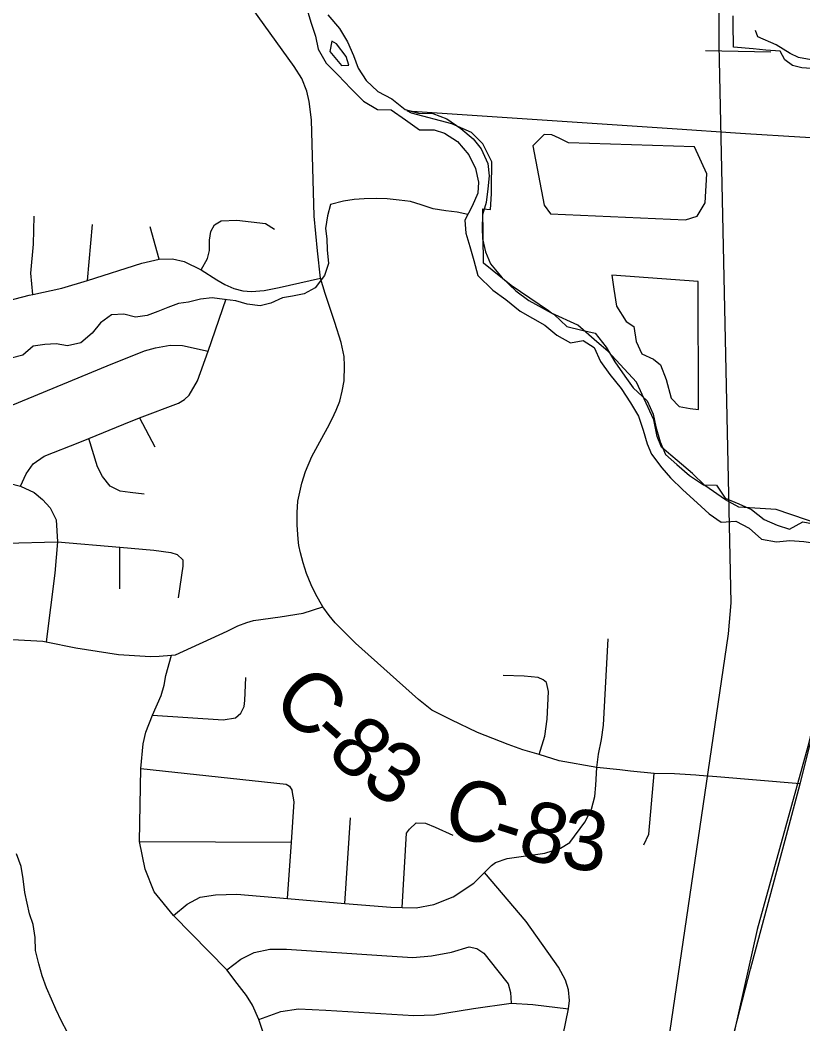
# Model space of a CAD drawing. Extents: x 0 to 34, y 0 to 22.
# Drawn here: x 4.322 to 5.063, y 18.158 to 19.107 of the extents above; entities that cross this region are included whole.
import ezdxf

# ---------------------------------------------------------------- set-up
doc = ezdxf.new("R2010")
doc.units = 0
for name, color, linetype in [('GM_X_City_Street', 7, 'Continuous'), ('GM_X_Corporation', 7, 'Continuous'), ('GM_X_County_Road', 7, 'Continuous'), ('GM_X_County_Road_Text', 7, 'Continuous'), ('GM_X_Major_River', 7, 'Continuous'), ('GM_X_Minor_Lake', 7, 'Continuous'), ('GM_X_Minor_River', 7, 'Continuous'), ('GM_X_Rail_Line', 7, 'Continuous'), ('GM_X_State_Route', 7, 'Continuous'), ('GM_X_Township_Road', 7, 'Continuous')]:
    doc.layers.add(name, color=color, linetype=linetype)

msp = doc.modelspace()

# ---------------------------------------------------------------- linework, layer by layer
at = {"layer": 'GM_X_City_Street'}
for p, q in [((4.38555, 18.86075), (4.39028, 18.91383)), ((4.45361, 18.88093), (4.44496, 18.9117)), ((4.43498, 18.731), (4.44926, 18.7035)), ((4.41612, 18.56929), (4.41612, 18.60863)), ((4.62907, 18.27172), (4.63468, 18.35253)), ((4.43502, 18.33033), (4.57869, 18.32953))]:
    msp.add_line(p, q, dxfattribs=at)
for points in [[(4.33382, 18.84764), (4.3321, 18.8678), (4.33448, 18.8951), (4.33533, 18.92167)], [(4.49327, 18.87101), (4.49915, 18.88166), (4.50099, 18.88937), (4.50099, 18.89892), (4.50246, 18.90737), (4.50576, 18.91362), (4.51201, 18.91729), (4.52707, 18.91802), (4.55425, 18.91472), (4.56269, 18.90958)], [(4.30388, 18.84021), (4.33059, 18.84694), (4.33382, 18.84764), (4.36149, 18.85359), (4.38555, 18.86075), (4.43708, 18.87726), (4.45361, 18.88093), (4.46609, 18.8813), (4.47712, 18.87872), (4.49327, 18.87101), (4.50815, 18.86146), (4.5155, 18.85706), (4.52413, 18.8532), (4.53276, 18.85099), (4.54084, 18.85044), (4.55296, 18.85154), (4.56692, 18.85412), (4.60604, 18.86311)], [(4.32218, 18.66628), (4.32761, 18.678), (4.33423, 18.68737), (4.34463, 18.69477), (4.37829, 18.70783), (4.38687, 18.71135), (4.42001, 18.72493), (4.43498, 18.731), (4.47165, 18.74487), (4.4774, 18.74819), (4.4819, 18.75231), (4.48987, 18.76581), (4.49974, 18.79403), (4.51698, 18.8434)], [(4.26401, 18.6743), (4.26874, 18.70071), (4.27171, 18.71813), (4.27638, 18.7245), (4.28715, 18.7319), (4.40426, 18.78028), (4.43947, 18.79445), (4.45016, 18.79729), (4.46388, 18.7997), (4.47565, 18.79949), (4.49974, 18.79403)], [(3.97531, 18.7522), (3.97875, 18.73865), (3.98594, 18.71497), (3.99255, 18.70194), (3.99813, 18.69576), (4.003, 18.69149), (4.01396, 18.68825), (4.0371, 18.68709), (4.13206, 18.68231), (4.20712, 18.67785), (4.26401, 18.6743), (4.28269, 18.67312), (4.2971, 18.67133), (4.31112, 18.66918), (4.32218, 18.66628), (4.33528, 18.66039), (4.34314, 18.65379), (4.35022, 18.64568), (4.35589, 18.63435), (4.3572, 18.61358), (4.35483, 18.58408), (4.34643, 18.51911)], [(4.43936, 18.65887), (4.42608, 18.66026), (4.41661, 18.66157), (4.4072, 18.6663), (4.39976, 18.67554), (4.39498, 18.68474), (4.38687, 18.71135)], [(4.28979, 18.58032), (4.29277, 18.59811), (4.29555, 18.60528), (4.29982, 18.61052), (4.30822, 18.61227), (4.3572, 18.61358)], [(4.3572, 18.61358), (4.41612, 18.60863), (4.4483, 18.60592), (4.4646, 18.60372), (4.47064, 18.60172), (4.47588, 18.59668), (4.47576, 18.59061), (4.47144, 18.56069)], [(4.31459, 18.52139), (4.34344, 18.51972), (4.34643, 18.51911), (4.37448, 18.51346), (4.41502, 18.50703), (4.44539, 18.50533), (4.45337, 18.50557), (4.46531, 18.50652), (4.46897, 18.5068), (4.51793, 18.52927), (4.5279, 18.53409), (4.53637, 18.53742), (4.54291, 18.53942), (4.56798, 18.54277), (4.58986, 18.54616), (4.60838, 18.55211)], [(4.86769, 18.40011), (4.86926, 18.41287), (4.87223, 18.42667), (4.87412, 18.4402), (4.87845, 18.5219)], [(4.55144, 18.15043), (4.54768, 18.16195), (4.54191, 18.17541), (4.53604, 18.18461), (4.52729, 18.1958), (4.51743, 18.20887), (4.4671, 18.26014), (4.44865, 18.28256), (4.44016, 18.30416), (4.43502, 18.33033), (4.43609, 18.39922), (4.43838, 18.4226), (4.44099, 18.43362), (4.44724, 18.44964), (4.45526, 18.46824), (4.45825, 18.47812), (4.45972, 18.48724), (4.46531, 18.50652)], [(4.44724, 18.44964), (4.51397, 18.44535), (4.52575, 18.44731), (4.53067, 18.45151), (4.53407, 18.45797), (4.53441, 18.46367), (4.53544, 18.48532)], [(4.81309, 18.41247), (4.81839, 18.42991), (4.82083, 18.44588), (4.82191, 18.47212), (4.82001, 18.48051), (4.81677, 18.48321), (4.81217, 18.48538), (4.79891, 18.48673), (4.77917, 18.48727)], [(4.43609, 18.39922), (4.57364, 18.38452), (4.5767, 18.38263), (4.57938, 18.37846)], [(4.4671, 18.26014), (4.47991, 18.27094), (4.49243, 18.27745), (4.50687, 18.2798), (4.52703, 18.28028), (4.57501, 18.27625), (4.62907, 18.27172), (4.67281, 18.26805), (4.68346, 18.26777), (4.69678, 18.26741), (4.7135, 18.27052), (4.73172, 18.27782), (4.75143, 18.29083), (4.76146, 18.30093), (4.76808, 18.3076), (4.77187, 18.31028), (4.78288, 18.31413), (4.81862, 18.31924), (4.83343, 18.32386), (4.84215, 18.32921), (4.85643, 18.34849), (4.86268, 18.36085), (4.86565, 18.37274), (4.8667, 18.38341), (4.86769, 18.40011)], [(4.91208, 18.32718), (4.91681, 18.33727), (4.92185, 18.39465)], [(4.57501, 18.27625), (4.57869, 18.32953), (4.58134, 18.36785), (4.57938, 18.37846)], [(4.68346, 18.26777), (4.68764, 18.33798), (4.69029, 18.34178), (4.69672, 18.34789), (4.70547, 18.34755), (4.71462, 18.3438), (4.73141, 18.33629)], [(4.83137, 18.21148), (4.8007, 18.25461), (4.76146, 18.30093)], [(4.51743, 18.20887), (4.53073, 18.21884), (4.54336, 18.22527), (4.55809, 18.22848), (4.57415, 18.22848), (4.66888, 18.22206), (4.69347, 18.22062), (4.71131, 18.22194), (4.73014, 18.2256), (4.74676, 18.23048), (4.75407, 18.22903), (4.76072, 18.22449), (4.77401, 18.20776), (4.78365, 18.19547), (4.78609, 18.18749), (4.78653, 18.17724)], [(4.55311, 18.11912), (4.6157, 18.11121), (4.70262, 18.10077), (4.74862, 18.10669), (4.80564, 18.11493), (4.81969, 18.12107), (4.83103, 18.13506), (4.83598, 18.14719), (4.84104, 18.17181), (4.84181, 18.17979), (4.84087, 18.18993), (4.8379, 18.19898), (4.83137, 18.21148)], [(4.54768, 18.16195), (4.5685, 18.16927), (4.58534, 18.17192), (4.61127, 18.17082), (4.69458, 18.16572), (4.71408, 18.16639), (4.75108, 18.17237), (4.78653, 18.17724), (4.80714, 18.17613), (4.84104, 18.17181)]]:
    msp.add_lwpolyline(points, dxfattribs=at)
at = {"layer": 'GM_X_Corporation'}
for points in [[(5.09183, 19.05987), (5.06178, 19.06204), (5.05293, 19.06419), (5.0457, 19.06974), (5.04133, 19.07774), (5.02768, 19.07888), (5.01579, 19.07987), (4.99707, 19.08143), (4.99701, 19.08595), (4.99685, 19.0995), (4.9968, 19.10372), (4.99665, 19.11137)], [(5.08109, 18.62959), (5.03738, 18.64436), (5.00204, 18.6466), (4.98957, 18.65331), (4.96997, 18.66686), (4.9582, 18.67838), (4.94366, 18.69069), (4.93777, 18.69567), (4.92878, 18.70328), (4.92467, 18.71345), (4.92169, 18.7292), (4.90529, 18.76469), (4.87812, 18.79405), (4.8678, 18.80297), (4.84977, 18.81855), (4.82493, 18.82998), (4.82191, 18.83204), (4.78662, 18.85616), (4.76058, 18.87714), (4.75996, 18.92857), (4.76702, 18.92817), (4.7681, 18.94298), (4.76814, 18.94819), (4.7683, 18.97308), (4.7598, 18.98999), (4.74916, 19.00098), (4.73043, 19.00896), (4.69231, 19.01911), (4.68815, 19.02126), (4.94366, 19.00433), (4.99883, 19.00063), (5.00831, 19.00003), (5.05997, 18.99684), (5.11381, 18.99352)]]:
    msp.add_lwpolyline(points, dxfattribs=at)
at = {"layer": 'GM_X_County_Road'}
msp.add_line((5.06027, 18.38488), (4.98121, 18.39138), dxfattribs=at)
for points in [[(4.61448, 18.54413), (4.60838, 18.55211), (4.60163, 18.56378), (4.59746, 18.57311), (4.5951, 18.57836), (4.59295, 18.58383), (4.58974, 18.5939), (4.58738, 18.60322), (4.58575, 18.61023), (4.58501, 18.6162), (4.58409, 18.62988), (4.584, 18.64145), (4.58483, 18.6522), (4.5885, 18.66909), (4.59199, 18.6802), (4.598, 18.69449), (4.60732, 18.71188), (4.61274, 18.72143), (4.61724, 18.73015), (4.6211, 18.73823), (4.62449, 18.74686), (4.62679, 18.75605), (4.62863, 18.76596), (4.62899, 18.78029), (4.62844, 18.7891), (4.62587, 18.80215), (4.61963, 18.82106), (4.61045, 18.84843), (4.60604, 18.86311), (4.60328, 18.88901), (4.60016, 18.9217), (4.59759, 19.01279), (4.59559, 19.03019), (4.59312, 19.03981), (4.58844, 19.05189), (4.5813, 19.06343), (4.51866, 19.15025)], [(4.8896, 18.39787), (4.86769, 18.40011), (4.83218, 18.40653), (4.81309, 18.41247), (4.79776, 18.41685), (4.78384, 18.42186), (4.7549, 18.43344), (4.72972, 18.44532), (4.71157, 18.4544), (4.69905, 18.46441), (4.6393, 18.51791), (4.61996, 18.53695), (4.61448, 18.54413)], [(4.9615, 18.39295), (4.94108, 18.39433), (4.92185, 18.39465), (4.89946, 18.39686), (4.8896, 18.39787)], [(4.98121, 18.39138), (4.96441, 18.39276), (4.9615, 18.39295)]]:
    msp.add_lwpolyline(points, dxfattribs=at)
at = {"layer": 'GM_X_Major_River'}
for points in [[(4.59429, 19.1148), (4.59727, 19.10416), (4.60139, 19.09199), (4.60398, 19.07983), (4.6115, 19.0665), (4.62282, 19.05506), (4.6349, 19.04247), (4.64698, 19.03064), (4.66021, 19.0226), (4.6731, 19.02216), (4.68671, 19.01298), (4.69994, 19.00343), (4.71359, 19.00336), (4.72344, 19.00028), (4.73592, 18.99224), (4.74647, 18.97967), (4.75286, 18.96673), (4.75583, 18.9538), (4.75502, 18.94356), (4.74965, 18.93106), (4.74276, 18.9178), (4.74384, 18.90565), (4.74757, 18.8931), (4.7513, 18.8798), (4.75502, 18.86573), (4.76936, 18.85161), (4.78146, 18.84282), (4.79506, 18.83175), (4.81851, 18.81873), (4.82984, 18.80918), (4.8427, 18.80191), (4.85485, 18.80412), (4.86505, 18.79762), (4.87106, 18.78431), (4.8801, 18.77211), (4.89065, 18.75878), (4.89969, 18.74506), (4.90722, 18.7325), (4.9117, 18.71919), (4.91543, 18.70626), (4.91956, 18.69675), (4.92935, 18.6838), (4.93727, 18.67427), (4.94897, 18.66283), (4.96257, 18.65061), (4.9739, 18.64031), (4.98524, 18.63228), (4.99927, 18.63335), (5.01176, 18.62646), (5.02346, 18.61615), (5.03787, 18.61381)], [(4.61324, 19.11205), (4.62418, 19.09909), (4.6317, 19.08652), (4.63733, 19.07359), (4.64182, 19.0618), (4.64935, 19.04999), (4.6603, 19.03969), (4.67354, 19.03279), (4.68638, 19.02248), (4.69888, 19.019), (4.71253, 19.01893), (4.72578, 19.01393), (4.73901, 19.00476), (4.75072, 18.99483), (4.75826, 18.9853), (4.76464, 18.97161), (4.76572, 18.95983), (4.76452, 18.94769), (4.76294, 18.93479), (4.75947, 18.92304), (4.75903, 18.91051), (4.75936, 18.90026), (4.76234, 18.88809), (4.76721, 18.87668), (4.77814, 18.86334), (4.79098, 18.85113), (4.80345, 18.84196), (4.81593, 18.83506), (4.82728, 18.82855), (4.83936, 18.81749), (4.85338, 18.814), (4.86626, 18.8109), (4.87644, 18.79795), (4.88471, 18.78386), (4.89413, 18.77053), (4.90204, 18.75948), (4.91525, 18.74689), (4.92088, 18.73433), (4.92347, 18.72255), (4.92758, 18.70811)], [(4.61691, 19.08736), (4.61497, 19.07749), (4.6259, 19.06415), (4.63311, 19.0645)], [(4.63311, 19.0645), (4.6305, 19.07286), (4.62145, 19.08468), (4.61691, 19.08736)], [(4.92758, 18.70811), (4.93283, 18.69631), (4.9434, 18.68677), (4.95549, 18.67646), (4.96872, 18.66767), (4.98085, 18.66723), (4.98914, 18.65504), (5.00201, 18.64966), (5.01412, 18.64429), (5.02621, 18.63474), (5.03832, 18.62937), (5.05006, 18.62552), (5.06261, 18.63267), (5.07436, 18.63034)], [(5.03787, 18.61381), (5.05039, 18.61489), (5.06366, 18.61406), (5.07654, 18.61211), (5.09206, 18.60558), (5.10531, 18.6002), (5.11817, 18.59292), (5.13026, 18.58414), (5.14276, 18.58028), (5.15562, 18.57187), (5.16504, 18.56005), (5.17105, 18.54788), (5.17516, 18.53495), (5.17737, 18.52241), (5.17769, 18.51064), (5.17422, 18.49851), (5.1719, 18.48827), (5.16576, 18.47539), (5.14138, 18.45348), (5.13336, 18.44175), (5.13216, 18.42999), (5.13248, 18.41746), (5.13143, 18.40594)]]:
    msp.add_lwpolyline(points, dxfattribs=at)
at = {"layer": 'GM_X_Minor_Lake'}
for points in [[(4.96001, 18.98734), (4.84089, 18.9912), (4.8322, 18.99547), (4.82502, 18.99858), (4.81782, 18.99903), (4.80708, 18.98813)], [(4.80708, 18.98813), (4.81792, 18.93222), (4.82391, 18.92381), (4.95175, 18.91835), (4.96278, 18.92165), (4.97012, 18.93448), (4.9719, 18.96179), (4.96001, 18.98734)], [(4.9637, 18.85977), (4.88179, 18.86591), (4.88394, 18.85261), (4.88644, 18.83664), (4.8954, 18.82213), (4.90257, 18.8175), (4.90508, 18.80305), (4.91029, 18.79161), (4.92124, 18.78657), (4.92802, 18.78118), (4.9332, 18.76709), (4.93796, 18.74958), (4.94547, 18.74153), (4.95608, 18.73991), (4.96404, 18.73869)], [(4.96404, 18.73869), (4.9637, 18.85977)]]:
    msp.add_lwpolyline(points, dxfattribs=at)
at = {"layer": 'GM_X_Minor_River'}
for points in [[(4.74566, 18.92338), (4.73546, 18.92543), (4.72486, 18.92667), (4.71275, 18.92868), (4.70142, 18.93259), (4.69121, 18.93572), (4.68061, 18.93696), (4.66925, 18.93821), (4.65902, 18.93831), (4.64765, 18.93804), (4.63817, 18.93737), (4.62793, 18.93595), (4.61577, 18.93265), (4.61264, 18.92205), (4.61102, 18.90991), (4.61207, 18.90041), (4.61235, 18.88977), (4.61375, 18.87685), (4.60986, 18.86549), (4.60104, 18.85381), (4.59075, 18.84821), (4.57974, 18.84604), (4.57026, 18.84461), (4.55922, 18.8394), (4.54896, 18.83684), (4.53685, 18.83847), (4.52589, 18.84162), (4.51529, 18.84286), (4.50356, 18.84449), (4.49255, 18.84308), (4.48116, 18.84053), (4.47168, 18.8391), (4.46179, 18.8354), (4.45228, 18.83169), (4.44201, 18.82762), (4.43101, 18.8262), (4.42005, 18.82896), (4.40829, 18.82832), (4.39799, 18.82082), (4.38994, 18.81103), (4.37925, 18.80201), (4.36672, 18.7991), (4.35613, 18.8011), (4.34513, 18.80044), (4.33412, 18.79865), (4.32458, 18.79039), (4.31356, 18.78746)], [(4.36653, 18.15011), (4.36094, 18.16042), (4.35573, 18.17148), (4.35165, 18.18101), (4.34682, 18.19169), (4.34276, 18.20312), (4.33945, 18.21455), (4.33653, 18.22711), (4.33626, 18.23926), (4.3341, 18.25182), (4.33078, 18.26172), (4.3286, 18.27199), (4.32642, 18.28189), (4.32464, 18.29482), (4.32285, 18.30661), (4.31841, 18.31842)]]:
    msp.add_lwpolyline(points, dxfattribs=at)
at = {"layer": 'GM_X_Rail_Line'}
for points in [[(4.80228, 17.25055), (4.8213, 17.366), (4.86303, 17.64736), (4.90372, 17.9242), (4.99245, 18.52676), (4.99499, 18.55593), (4.98355, 19.08363), (4.98587, 19.75382), (4.99256, 19.90285), (5.013, 20.2642), (5.02024, 20.38635), (5.05041, 20.9)], [(5.013, 20.2642), (5.1449, 19.80142), (5.15727, 19.72918), (5.15969, 19.50896), (5.13444, 19.0127), (5.12013, 18.63864), (5.06738, 18.42023), (5.01943, 18.24707), (4.96758, 18.0163), (4.96155, 17.92727), (4.95651, 17.64256), (4.86303, 17.64736)]]:
    msp.add_lwpolyline(points, dxfattribs=at)
at = {"layer": 'GM_X_State_Route'}
for points in [[(5.0472, 18.33612), (5.06027, 18.38488), (5.0795, 18.46117), (5.1045, 18.55414), (5.10555, 18.55897)], [(4.95945, 17.87106), (4.96194, 17.92079), (4.96695, 17.99186), (4.97424, 18.03982), (4.98786, 18.11159), (5.01323, 18.20936), (5.0472, 18.33612)]]:
    msp.add_lwpolyline(points, dxfattribs=at)
at = {"layer": 'GM_X_Township_Road'}
msp.add_line((4.97042, 19.07854), (5.03227, 19.07717), dxfattribs=at)
msp.add_lwpolyline([(5.1325, 18.91193), (5.12293, 18.91011), (5.11676, 18.91231), (5.11234, 18.91408), (5.10882, 18.91783), (5.10926, 18.92511), (5.11279, 18.93327), (5.11587, 18.94054), (5.11896, 18.95444), (5.12028, 18.99899), (5.12249, 19.03736), (5.11984, 19.05104), (5.11499, 19.05898), (5.10926, 19.06382), (5.09692, 19.06779), (5.07046, 19.06956), (5.05855, 19.07176), (5.05062, 19.07573), (5.03739, 19.08368), (5.02008, 19.09142), (5.01777, 19.09728)], dxfattribs=at)

# ---------------------------------------------------------------- texts
at = {"layer": 'GM_X_County_Road_Text'}
for s, rotation, p in [('C', 317.07338, (4.55796, 18.46021)), ('-', 318.0911, (4.59269, 18.42792)), ('8', 318.65272, (4.61036, 18.41207)), ('3', 325.91301, (4.64264, 18.38432)), ('C', 338.96613, (4.71821, 18.34236)), ('8', 345.68101, (4.79088, 18.31618)), ('3', 352.66076, (4.83221, 18.3061)), ('-', 341.95816, (4.76482, 18.32453))]:
    msp.add_text(s, height=0.05682, rotation=rotation, dxfattribs=at).set_placement(p)

doc.saveas('drawing.dxf')
